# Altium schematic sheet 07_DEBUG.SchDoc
size A2; ApprovedBy: DNP; CheckedBy: DNP; Author: DNP; CompanyName: Google LLC; DrawnBy: DNP; Engineer: Bangfei/Michael/Leo; Organization: Google LLC; Address1: 1600 Amphitheatre Parkway; Address2: Mountain View, CA 94043; Address3: DNP; Address4: DNP; DocumentNumber: DNP; Revision: PVT; SheetNumber: 7; SheetTotal: 11; VersionControl_RevNumber: DNP; IsUserConfigurable: DNP
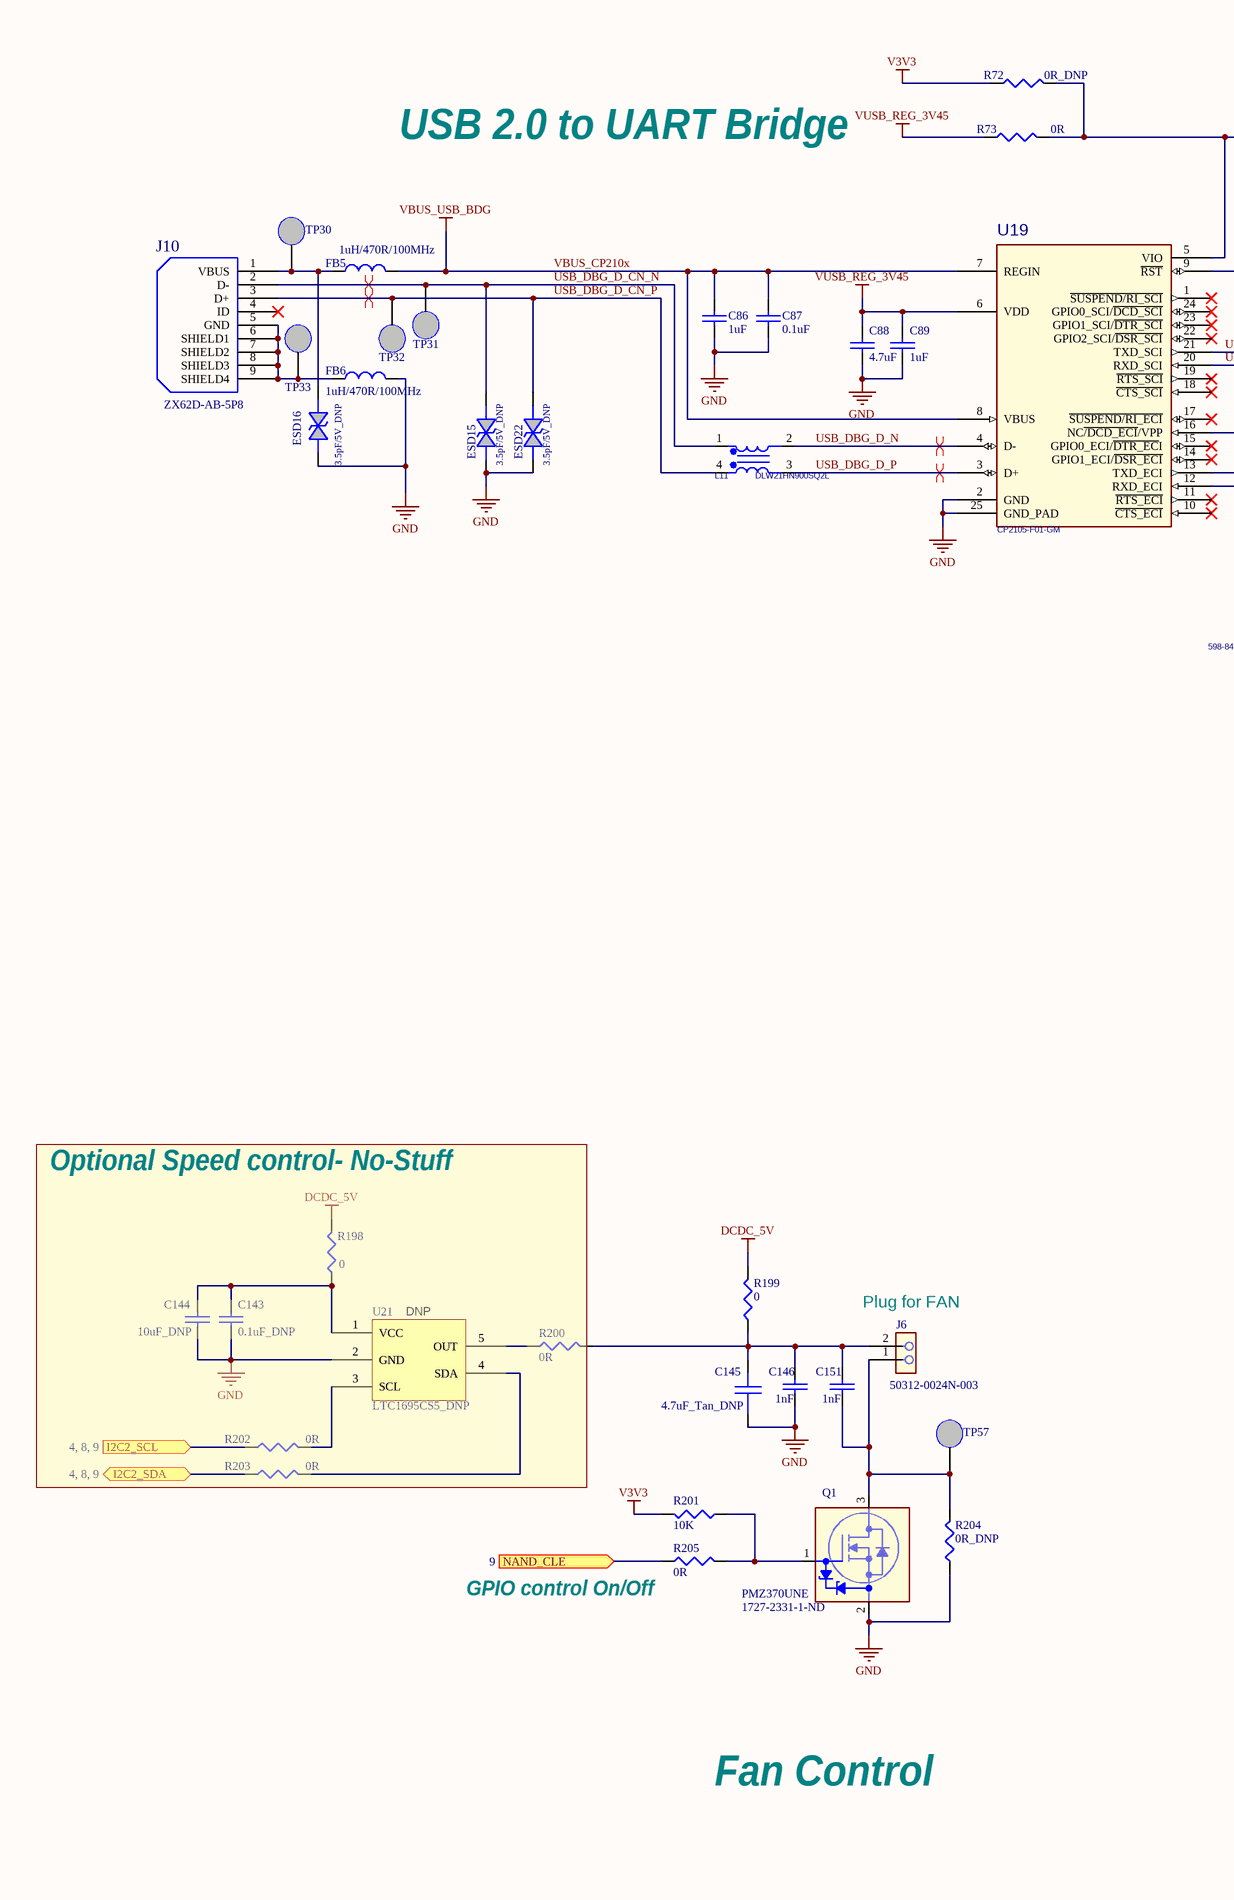
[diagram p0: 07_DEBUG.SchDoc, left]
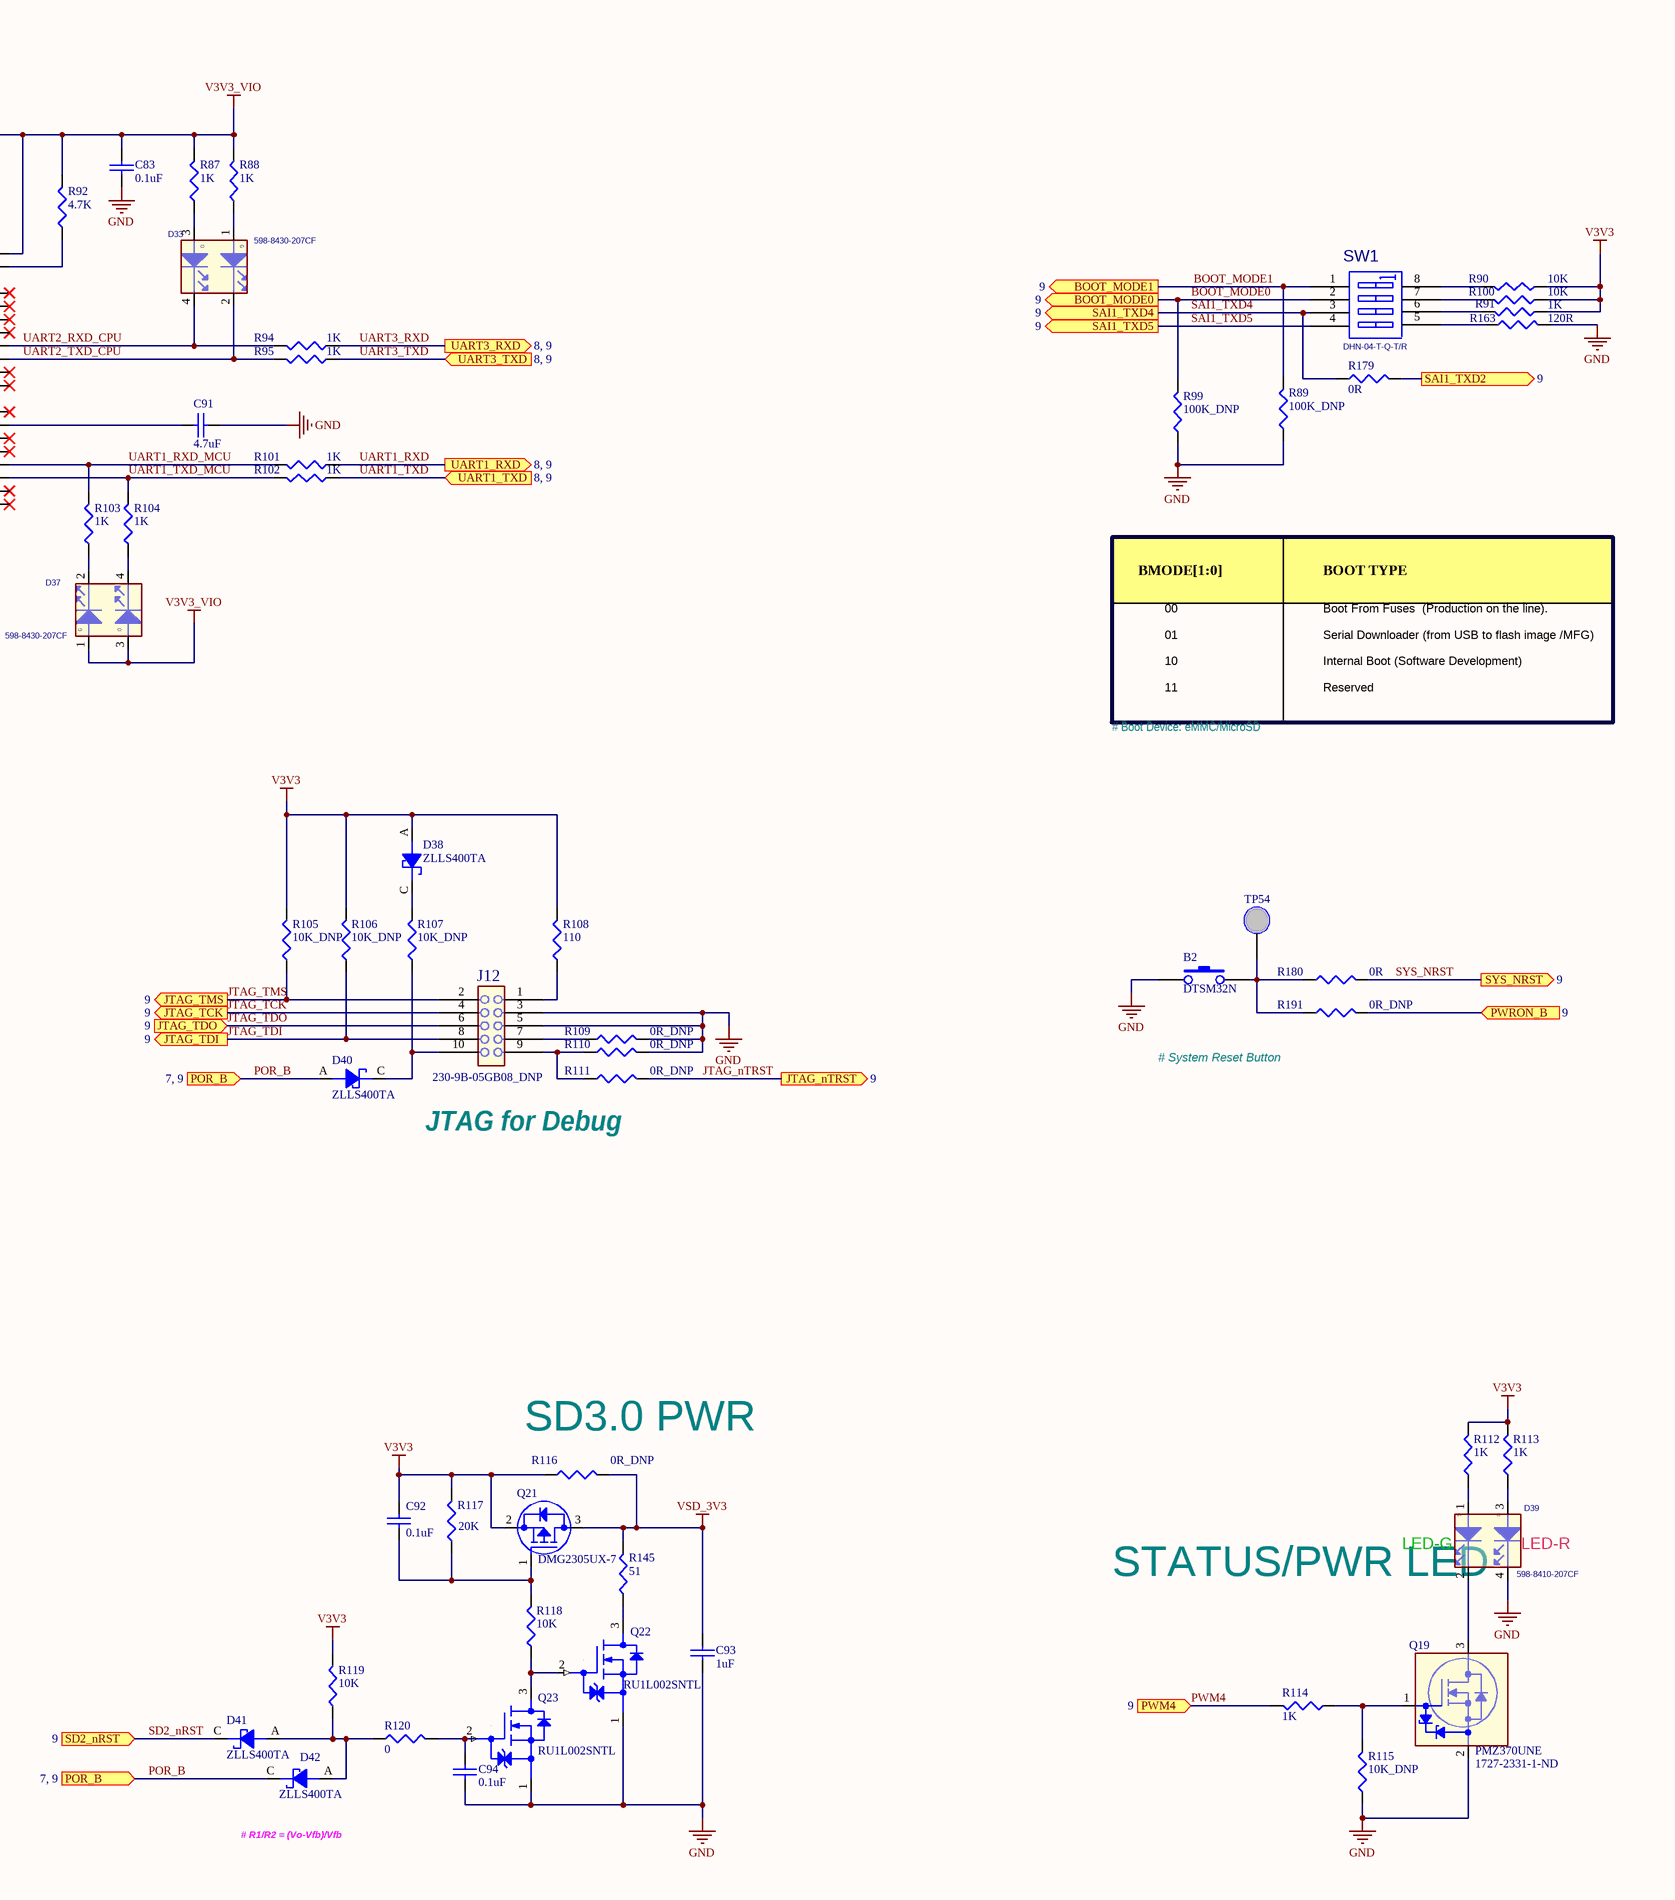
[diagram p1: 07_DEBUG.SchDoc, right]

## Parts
B2  DTSM32N  [sw2-6_0x3_5-h5_2]
C83  value 0.1uF  [0201]  (hidden comment: 0.1uF/10V)
C86  value 1uF  [0201]  (hidden comment: 1uF/6.3V)
C87  value 0.1uF  [0201]  (hidden comment: 0.1uF/10V)
C88  value 4.7uF  [0402]  (hidden comment: 4.7uF/10V)
C89  value 1uF  [0201]  (hidden comment: 1uF/6.3V)
C91  value 4.7uF  [0402]  (hidden comment: 4.7uF/10V)
C92  value 0.1uF  [0201]  (hidden comment: 0.1uF/10V)
C93  value 1uF  [0201]  (hidden comment: 1uF/6.3V)
C94  value 0.1uF  [0201]  (hidden comment: 0.1uF/10V)
C143  value 0.1uF_DNP  [0201]  (hidden comment: 0.1uF/10V)
C144  value 10uF_DNP  [0402]  (hidden comment: 10uF/10V)
C145  value 4.7uF_Tan_DNP  [1206]  (hidden comment: 47uF/25V)
C146  value 1nF  [0201]  (hidden comment: 1nF/25V)
C151  value 1nF  [0201]  (hidden comment: 1nF/25V)
D33  598-8430-207CF  [LED_0606]
D37  598-8430-207CF  [LED_0606]
D38  ZLLS400TA  [SOD323]
D39  598-8410-207CF  [LED_0606]
D40  ZLLS400TA  [SOD323]
D41  ZLLS400TA  [SOD323]
D42  ZLLS400TA  [SOD323]
ESD15  3.5pF/5V_DNP  [0201]
ESD16  3.5pF/5V_DNP  [0201]
ESD22  3.5pF/5V_DNP  [0201]
FB5  1uH/470R/100MHz  [0603]
FB6  1uH/470R/100MHz  [0603]
J6  50312-0024N-003  [SIP2-2MM-6X4_8MM-50312]
J10  ZX62D-AB-5P8  [USB5-0_65-ZX62D-AB-5P8]
J12  230-9B-05GB08_DNP  [HD2X5-1_27MM-3_35MM]
L11  DLW21HN900SQ2L  [IND4_CHOKE_0805]
Q1  PMZ370UNE  Supplier Part Number 1: 1727-2331-1-ND  [DFN10106B]
Q19  PMZ370UNE  Supplier Part Number 1: 1727-2331-1-ND  [DFN10106B]
Q21  DMG2305UX-7  [SOT-23]
Q22  RU1L002SNTL  [SOT323_3]
Q23  RU1L002SNTL  [SOT323_3]
R72  0R_DNP  [0201]
R73  0R  [0201]
R87  value 1K  [0201]  (hidden comment: 1K/1%)
R88  value 1K  [0201]  (hidden comment: 1K/1%)
R89  100K_DNP  [0201]
R90  10K  [0201]
R91  value 1K  [0201]  (hidden comment: 1K/1%)
R92  4.7K  [0201]
R94  value 1K  [0201]  (hidden comment: 1K/1%)
R95  value 1K  [0201]  (hidden comment: 1K/1%)
R99  100K_DNP  [0201]
R100  10K  [0201]
R101  value 1K  [0201]  (hidden comment: 1K/1%)
R102  value 1K  [0201]  (hidden comment: 1K/1%)
R103  value 1K  [0201]  (hidden comment: 1K/1%)
R104  value 1K  [0201]  (hidden comment: 1K/1%)
R105  10K_DNP  [0201]
R106  10K_DNP  [0201]
R107  10K_DNP  [0201]
R108  110  [0201]
R109  0R_DNP  [0201]
R110  0R_DNP  [0201]
R111  0R_DNP  [0201]
R112  value 1K  [0201]  (hidden comment: 1K/1%)
R113  value 1K  [0201]  (hidden comment: 1K/1%)
R114  value 1K  [0201]  (hidden comment: 1K/1%)
R115  10K_DNP  [0201]
R116  0R_DNP  [0402]
R117  20K  [0201]
R118  10K  [0201]
R119  10K  [0201]
R120  value 0  [0402]  (hidden comment: 0R)
R145  51  [0402]
R163  120R  [0402]
R179  0R  [0201]
R180  value 0R  [0201]  (hidden comment: 0R_DNP)
R191  0R_DNP  [0201]
R198  value 0  [0402]  (hidden comment: 0R)
R199  value 0  [0402]  (hidden comment: 0R)
R200  0R  [0402]
R201  10K  [0201]
R202  value 0R  [0201]  (hidden comment: 0)
R203  value 0R  [0201]  (hidden comment: 0)
R204  value 0R_DNP  [0402]  (hidden comment: 0R)
R205  value 0R  [0201]  (hidden comment: 0R_DNP)
SW1  DHN-04-T-Q-T/R  [SW_DIP4_SM]
TP30  TP NM  [TP_SMD_L]  (value not drawn)  (no BOM)
TP31  TP NM  [TP_SMD]  (value not drawn)  (no BOM)
TP32  TP NM  [TP_SMD]  (value not drawn)  (no BOM)
TP33  TP NM  [TP_SMD_L]  (value not drawn)  (no BOM)
TP54  TP NM  [TP_SMD_L]  (value not drawn)  (no BOM)
TP57  TP NM  [TP_SMD_L]  (value not drawn)  (no BOM)
U19  CP2105-F01-GM  [QFN24_0P5_4X4_EP]
U21  LTC1695CS5_DNP  [SOT23-S5-1695f]

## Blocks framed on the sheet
Optional Speed control- No-Stuff: C143 C144 R198 R200 R202 R203 U21

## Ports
BOOT_MODE0 (out, see 9), BOOT_MODE1 (out, see 9), I2C2_SCL (in, see 4, 8, 9), I2C2_SDA (bidir, see 4, 8, 9), JTAG_nTRST (out, see 9), JTAG_TCK (out, see 9), JTAG_TDI (out, see 9), JTAG_TDO (in, see 9), JTAG_TMS (out, see 9), NAND_CLE (in, see 9), POR_B (in, see 7, 9), PWM4 (in, see 9), PWRON_B (in, see 9), SAI1_TXD2 (out, see 9), SAI1_TXD4 (out, see 9), SAI1_TXD5 (out, see 9), SD2_nRST (in, see 9), SYS_NRST (out, see 9), UART1_RXD (out, see 8, 9), UART1_TXD (in, see 8, 9), UART3_RXD (out, see 8, 9), UART3_TXD (in, see 8, 9)

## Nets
DCDC_5V: R198.2 R199.2
GND: B2.1 C83.2 C86.2 C87.2 C88.2 C89.2 C91.2 C93.2 C94.2 C143.2 C144.2 C145.2 C146.1 D39.4(CATHODE2) ESD15.1 ESD16.1 ESD22.1 FB6.2 J12.3 J12.5 Q1.2(SOURCE) Q19.2(SOURCE) Q22.1(SOURCE) Q23.1(SOURCE) R89.1 R99.1 R109.2 R110.2 R115.1 R163.2 R204.1 U19.2(GND) U19.25(GND_PAD) U21.2(GND)
V3V3: C92.1 D38.A Q21.2(SOURCE) R72.1 R90.1 R91.1 R100.1 R105.2 R106.2 R108.2 R112.2 R113.2 R116.1 R117.2 R119.2 R201.2
V3V3_VIO: C83.1 D37.1(ANODE1) D37.3(ANODE2) R72.2 R73.2 R87.2 R88.2 R92.2 U19.5(VIO)
VBUS_CP210x: C86.1 C87.1 FB5.2 U19.7(REGIN) U19.8(VBUS)  [also labelled VBUS_USB_BDG]
VSD_3V3: C93.1 Q21.3(DRAIN) R116.2 R145.2
VUSB_REG_3V45: C88.1 C89.1 R73.1 U19.6(VDD)
BOOT_MODE0: R99.2 SW1.2(A2) ; port BOOT_MODE0
BOOT_MODE1: R89.2 SW1.1(A1) ; port BOOT_MODE1
I2C2_SCL: R202.1 ; port I2C2_SCL
I2C2_SDA: R203.1 ; port I2C2_SDA
JTAG_nTRST: R111.2 ; port JTAG_nTRST
JTAG_TCK: J12.4 ; port JTAG_TCK
JTAG_TDI: J12.8 R106.1 ; port JTAG_TDI
JTAG_TDO: J12.6 ; port JTAG_TDO
JTAG_TMS: J12.2 R105.1 ; port JTAG_TMS
NAND_CLE: R205.1 ; port NAND_CLE
POR_B: D40.A D42.C ; port POR_B
PWM4: R114.2 ; port PWM4
PWRON_B: R191.2 ; port PWRON_B
SAI1_TXD2: R179.2 ; port SAI1_TXD2
SAI1_TXD4: R179.1 SW1.3(A3) ; port SAI1_TXD4
SAI1_TXD5: SW1.4(A4) ; port SAI1_TXD5
SD2_nRST: D41.C ; port SD2_nRST
SYS_NRST: R180.2 ; port SYS_NRST
UART1_RXD: R101.1 ; port UART1_RXD
UART1_RXD_MCU: R101.2 R103.2 U19.13(TXD_ECI)
UART1_TXD: R102.1 ; port UART1_TXD
UART1_TXD_MCU: R102.2 R104.2 U19.12(RXD_ECI)
UART2_RXD_CPU: D33.4(CATHODE2) R94.2 U19.21(TXD_SCI)
UART2_TXD_CPU: D33.2(CATHODE1) R95.2 U19.20(RXD_SCI)
UART3_RXD: R94.1 ; port UART3_RXD
UART3_TXD: R95.1 ; port UART3_TXD
USB_DBG_D_CN_N: ESD15.2 J10.2(D-) L11.1 TP31.1
USB_DBG_D_CN_P: ESD22.2 J10.3(D+) L11.4 TP32.1
USB_DBG_D_N: L11.2 U19.4(D-)
USB_DBG_D_P: L11.3 U19.3(D+)
NetB2_2: B2.2 R180.1 R191.1 TP54.1
NetC91_1: C91.1 U19.16(NC~{/DCD_ECI}/VPP)
NetC92_2: C92.2 Q21.1(GATE) R117.1 R118.2
NetC94_1: C94.1 Q23.2(GATE) R120.2
NetC143_1: C143.1 C144.1 R198.1 U21.1(VCC)
NetC145_1: C145.1 C146.2 C151.2 J6.2 R199.1 R200.2
NetC151_1: C151.1 J6.1 Q1.3(DRAIN) R204.2 TP57.1
NetD33_1: D33.1(ANODE1) R88.1
NetD33_3: D33.3(ANODE2) R87.1
NetD37_2: D37.2(CATHODE1) R103.1
NetD37_4: D37.4(CATHODE2) R104.1
NetD38_C: D38.C R107.2
NetD39_1: D39.1(ANODE1) R112.1
NetD39_2: D39.2(CATHODE1) Q19.3(DRAIN)
NetD39_3: D39.3(ANODE2) R113.1
NetD40_C: D40.C J12.10 R107.1
NetD41_A: D41.A D42.A R119.1 R120.1
NetESD16_2: ESD16.2 FB5.1 J10.1(VBUS) TP30.1
NetFB6_1: FB6.1 J10.5(GND) J10.6(SHIELD1) J10.7(SHIELD2) J10.8(SHIELD3) J10.9(SHIELD4) TP33.1
NetJ12_1: J12.1 R108.1
NetJ12_7: J12.7 R109.1
NetJ12_9: J12.9 R110.1 R111.1
NetQ1_1: Q1.1(GATE) R201.1 R205.2
NetQ19_1: Q19.1(GATE) R114.1 R115.2
NetQ22_2: Q22.2(GATE) Q23.3(DRAIN) R118.1
NetQ22_3: Q22.3(DRAIN) R145.1
NetR90_2: R90.2 SW1.8(B1)
NetR91_2: R91.2 SW1.6(B3)
NetR92_1: R92.1 U19.9(~{RST})
NetR100_2: R100.2 SW1.7(B2)
NetR163_1: R163.1 SW1.5(B4)
NetR200_1: R200.1 U21.5(OUT)
NetR202_2: R202.2 U21.3(SCL)
NetR203_2: R203.2 U21.4(SDA)

Not connected (* = marked no-connect by the designer): J10 4(ID)*; U19 1(~{SUSPEND/RI_SCI})* 10(~{CTS_ECI})* 11(~{RTS_ECI})* 14(GPIO1_ECI/~{DSR_ECI})* 15(GPIO0_ECI/~{DTR_EC}I)* 17(~{SUSPEND/RI_ECI})* 18(~{CTS_SCI})* 19(~{RTS_SCI})* 22(GPIO2_SCI/~{DSR_SCI})* 23(GPIO1_SCI/~{DTR_SCI})* 24(GPIO0_SCI/~{DCD_SCI})*

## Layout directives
differential pair: USB_DBG_D_CN_N, USB_DBG_D_CN_P, USB_DBG_D_N, USB_DBG_D_P

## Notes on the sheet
- USB 2.0 to UART Bridge
- BMODE[1:0]
- 00
- 01
- BOOT TYPE
- Boot From Fuses  (Production on the line).
- Serial Downloader (from USB to flash image /MFG)
- 10
- 11
- Internal Boot (Software Development)
- Reserved
- # Boot Device: eMMC/MicroSD
- # System Reset Button
- (near R111) JTAG for Debug
- (near U21) DNP
- (near J6) Plug for FAN
- (near R116) SD3.0 PWR
- (near D39) LED-G
- (near D39) LED-R
- (near R205) GPIO control On/Off
- STATUS/PWR LED
- Fan Control
- # R1/R2 = (Vo-Vfb)/Vfb

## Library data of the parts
B2 = SW-PB: Tact Switch; MPN: DTSM-32N-Q-TR; QCI MPN: DTSM-32N-Q-T/R; Function Code: DBG; QPN: DHP00032N02; QPN Description: SWITCH TACT SMD DTSM-61N-S-Q-T/R
C83 C87 C92 C94 = CAP_0201_0.1uF: CAP CER 0.1UF 10V 10% X5R 0201; MPN: C0603X5R1A104K030BC; QCI MPN: GRM033R61A104K; QPN: CH4102K9E00; QPN Description: CAP CHIP 0.1U 10V(+-10%,X5R,0201); Function Code: DBG
C86 C89 C93 = CAP_0201_1.0uF: CAP CER 1UF 6.3V 20% X5R 0201; MPN: C0603X5R0J105M030BC; QCI MPN: GRM033R60J105M; QPN: CH5101M9E02; QPN Description: CAP CHIP 1UF 6.3V(+-20%,X5R,0201); Function Code: DBG
C88 C91 = CAP_0402_4.7uF: CAP CER 4.7UF 10V 20% X5R 0402; MPN: C1005X5R1A475M050BC; QCI MPN: GRM155R61A475M; QPN: CH5472M9B01; QPN Description: CAP CHIP 4.7U 10V(+-20%,X5R,0402); Function Code: DBG
C143 = CAP_0201_0.1uF: CAP CER 0.1UF 10V 10% X5R 0201; MPN: C0603X5R1A104K030BC; QCI MPN: GRM033R61A104K; QPN: CH4102K9E00; QPN Description: CAP CHIP 0.1U 10V(+-10%,X5R,0201); Function Code: ADO
C144 = CAP_0402_10uF: CAP CER 10UF 10V 20% X5R 0402; MPN: CL05A106MP5NUNC; QCI MPN: GRM155R61A106M; QPN: CH6102M9B00; QPN Description: CAP CHIP 10U 10V (+-20%, X5R, 0402)'; Function Code: LAN
C145 = CAP_1206_47uF_25V: CAP CER 47UF 25V 20% 1206; MPN: C3216JB1E476M160AC; Function Code: USB
C146 C151 = CAP_0201_1.0nF: CAP CER 1nF 25V 10% X7R 0201; MPN: GRM033R71E102KA01D; QCI MPN: GRM033R71E102K; QPN: CH2104K1E00; QPN Description: CAP CHIP 1000P 25V(+-10%,X7R,0201); Function Code: SPK
D33 D37 = LED4_DUAL_OG: LED BI-COLOR ORANGE/GRN 20MA SMD 0606; Function Code: DBG; QPN: BEAG0003ZA0; QPN Description: LED SMD 4P O/G(598-8430-207CF)
D38 D40-D42 = DIODE_SCHTKY: DIODE SCHOTTKY 40V 520MA SOD323; Function Code: DBG; QPN: BCS400TA000; QPN Description: DIODE SCHOTTKY ZLLS400TA(20V,1A)
D39 = LED4_DUAL_OG: LED BI-COLOR ORANGE/GRN 20MA SMD 0606; MPN: 598-8430-207CF; Function Code: DBG; QPN: BEAG0003ZA0; QPN Description: LED SMD 4P O/G(598-8430-207CF)
ESD15 ESD16 ESD22 = DIODE BI-DIR TRIG: DIODE TVS 15kV 10V 50A 8pF SMT RoHS; MPN: DESD5V0V1BCSP-7; QPN: BC5V0V1BZ02; QPN Description: DIODE ESD SMD DESD5V0V1BCSP-7 6V,DSN0603; Function Code: DBG; DNP: V
FB5 FB6 = INDUCTOR_BLM18PG471SN1: FERRITE CHIP 470 OHM 1.0A 0603; QCI MPN: BLM18PG471SN1D; QPN: CX8PG471000; QPN Description: EMI FILTER BLM18PG471SN1D(470,1000MA); Function Code: DBG
J6 = HEADER 1X2: CONN DIP HEADER 2P 1R MS(P2.0,H6.2); Function Code: DCD; QPN: DFHD02MS182
J10 = USB_AB: Micro USB AB Connector, Standard SMT + DIP; QPN: DFHS05FR095; QPN Description: CONN DIP MICRO USB 5P 1R FR(P0.65,H2.95); Function Code: DBG
J12 = HEADER 2x5: 2x5 pin header, 1.27mm pitch, THM; DNP: V; Function Code: DBG
L11 = IND_CMC_DLW21: IND CHK 90 OHM@100MHZ 330MA 25% 0805; QPN: CX1HN900000; QPN Description: EMI FILTER DLW21HN900SQ2L(90,330MA); Function Code: DBG
Q1 = NMOS_NX3008NBK: N-Channel 30V 590mA, SMT DFN1006B-3; MPN: PMZB550UNEYL; Function Code: USB; QPN: BAM03700000; QPN Description: TRANS MOSFET PMZ370UNE (30V,0.9 A,0.36W)
Q19 = NMOS_NX3008NBK: N-Channel 30V 590mA, SMT DFN1006B-3; MPN: PMZB550UNEYL; Function Code: DBG; QPN: BAM03700000; QPN Description: TRANS MOSFET PMZ370UNE (30V,0.9 A,0.36W)
Q21 = MOSFET_P: P-Channel 20V 4.2A (Ta) 1.4W (Ta) Surface Mount SOT-23; Function Code: DBG; QPN: BAM23050008; QPN Description: TRANS MOS DMG2305UX-7(20V,4.2A,1.4W)
Q22 Q23 = 2SK3018: N-Channel 30V 100mA (Ta) 200mW (Ta) Surface Mount SOT-323; QPN: BAM1L000000; QPN Description: TRANS MOS RU1L002SN(60V,0.25A,0.2W)SC-85; Function Code: DBG
R72 R109-R111 R180 R191 R202 R203 = R_0201_0: RES SMD 0.0OHM JUMPER 1/20W 0201; MPN: ERJ-1GN0R00C; QCI MPN: RC0201JR-130RL; DNP: V; QPN: CS00001JE18; QPN Description: RES CHIP 0(1/20W,+-5%,0201); Function Code: DBG
R73 = R_0201_0: RES SMD 0.0OHM JUMPER 1/20W 0201; MPN: ERJ-1GN0R00C; QCI MPN: RC0201JR-130RL; QPN: CS00001JE18; QPN Description: RES CHIP 0(1/20W,+-5%,0201); Function Code: DBG
R87 R88 R94 R95 R101-R104 R112-R114 = R_0201_1K: RES SMD 1K OHM 1% 1/20W 0201; MPN: ERJ-1GEF1001C; QCI MPN: RC0201FR-131KL; QPN: CS21001FE04; QPN Description: RES CHIP 1K 1/20W +-1%(0201); Function Code: DBG
R89 R99 = R_0201_100K: RES SMD 100K OHM JUMPER 1/20W  0201; MPN: ERJ-1GEF1003C; QCI MPN: RC0201FR-07100KL; DNP: V; QPN: TS41001FE04; QPN Description: RES CHIP 100K 1/20W +-1%(0201)EMS-SEL; Function Code: DBG
R90 R100 R118 R119 = R_0201_10K: RES SMD 10K OHM JUMPER 1/20W  0201; MPN: ERJ-1GEF103C; QCI MPN: RC0201JR-1310KL; QPN: CS31001JE16; QPN Description: RES CHIP 10K 1/20W +-5%(0201); Function Code: DBG
R91 = R_0201_1K: RES SMD 1K OHM 1% 1/20W 0201; MPN: ERJ-1GEF1001C; QCI MPN: RC0201FR-131KL; QPN: CS21001FE04; QPN Description: RES CHIP 1K 1/20W +-1%(0201); Function Code: USB
R92 = R_0201_4.7K: RES SMD 4.7K OHM 1% 1/20W 0201; MPN: ERJ-1GEF4701C; QCI MPN: RC0201FR-134K7L; QPN: CS24701FE00; QPN Description: RES CHIP 4.7K 1/20W +-1%(0201; Function Code: DBG
R105-R107 R115 = R_0201_10K: RES SMD 10K OHM JUMPER 1/20W  0201; MPN: ERJ-1GEF103C; QCI MPN: RC0201JR-1310KL; DNP: V; QPN: CS31001JE16; QPN Description: RES CHIP 10K 1/20W +-5%(0201); Function Code: DBG
R108 = R_0201_110: RES SMD 110 OHM 1% 1/20W 0201; MPN: ERJ-1GEF1100C; QCI MPN: RC0201FR-07110RL; QPN: CS11101FE00; QPN Description: RES CHIP 110 1/20W +-1% (0201); Function Code: DBG
R116 = R_0402_0: RES SMD 0.0 OHM JUMPER 1/10W  0402; MPN: ERJ-2GE0R00X; QCI MPN: RC0402FR-070RL; DNP: V; QPN: CS00002FB00; QPN Description: RES CHIP 0 1/16W +-1%(0402); Function Code: DBG
R117 = R_0201_20K: RES SMD 20K OHM 1% 1/20W 0201; MPN: ERJ-1GEF2002C; QCI MPN: RC0201FR-0720KL; QPN: CS32001FE00; QPN Description: RES CHIP 20K 1/20W +-1%(0201); Function Code: DBG
R120 R198-R200 = R_0402_0: RES SMD 0.0 OHM JUMPER 1/10W  0402; MPN: ERJ-2GE0R00X; QCI MPN: RC0402FR-070RL; QPN: CS00002FB00; QPN Description: RES CHIP 0 1/16W +-1%(0402); Function Code: DBG
R145 = R_0402_51: RES SMD 51 OHM 1% 1/10W 0402; MPN: ERJ-2RKF51R0X; QCI MPN: RC0402FR-0751RL; QPN: CS05102FB09; QPN Description: RES CHIP 51 1/16W +-1% (0402); Function Code: DBG
R163 = R_0402_120: RES SMD 120 OHM 1% 1/10W 0402; MPN: RC0402FR-07120R; QPN: CS11202FB03; QPN Description: RES CHIP 120 1/16W +-1%(0402); Function Code: DBG
R179 = R_0805_0: RES SMD 0.0OHM JUMPER 1/20W 0201; MPN: ERJ-1GN0R00C; QCI MPN: RC0201JR-130RL; QPN: CS00001JE18; QPN Description: RES CHIP 0(1/20W,+-5%,0201); Function Code: SPK
R201 = R_0201_10K: RES SMD 10K OHM JUMPER 1/20W  0201; MPN: ERJ-1GEF103C; QCI MPN: RC0201JR-1310KL; QPN: CS31001JE16; QPN Description: RES CHIP 10K 1/20W +-5%(0201); Function Code: USB
R204 = R_0402_0: RES SMD 0.0 OHM JUMPER 1/10W  0402; MPN: ERJ-2GE0R00X; QCI MPN: RC0402FR-070RL; QPN: CS00002FB00; QPN Description: RES CHIP 0 1/16W +-1%(0402); Function Code: USB
R205 = R_0201_0: RES SMD 0.0OHM JUMPER 1/20W 0201; MPN: ERJ-1GN0R00C; QCI MPN: RC0201JR-130RL; DNP: V; QPN: CS00001JE18; QPN Description: RES CHIP 0(1/20W,+-5%,0201); Function Code: USB
SW1 = SW_DIP-4: SW 4P SPST DIP 25MA 24V SMT; Function Code: DBG; QPN: DHDDHN04T00; QPN Description: SWITCH DIP(DHN-04-T-Q-T/R)
TP30 TP33 TP54 TP57 = TP_L: TEST POINT (Large)
TP31 TP32 = TP: TEST POIN
U19 = CP2105_QFN24P: IC XCVR USB TO DUAL-UART 3.0-3.6V QFN24; QPN: AL002105001; QPN Description: IC CTRL(24P)CP2105-F01-GM(QFN); Function Code: DBG
U21 = LTC1695: LTC1695CS5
